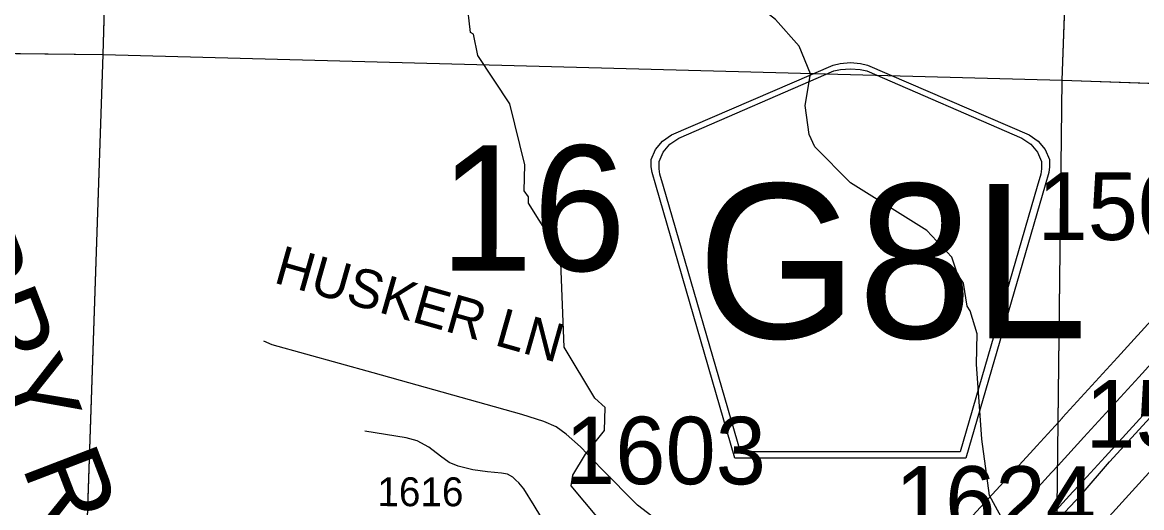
# Model space of a CAD drawing. Extents: x -132.8 to -73.3, y -60 to -26.
# Drawn here: x -119.904 to -118.744, y -46.837 to -46.334 of the extents above; entities that cross this region are included whole.
import ezdxf

# ---------------------------------------------------------------- set-up
doc = ezdxf.new("R2010")
doc.units = 0
for name, color, linetype in [('tdCoHydroRiver', 7, 'Continuous'), ('tdCoRRCL', 7, 'Continuous'), ('tdCoSecRdNmbr', 7, 'Continuous'), ('tdCoSecRdTxt', 7, 'Continuous'), ('tdCoSecRteBand', 7, 'Continuous'), ('tdCoSecRteCL', 7, 'Continuous'), ('tdCoSectLine', 7, 'Continuous'), ('tdCoSectLinePart', 7, 'Continuous'), ('tdCoSectNmbr', 7, 'Continuous'), ('tdCoShieldCoRteHrd', 7, 'Continuous'), ('tdCoSurfAsphalt', 7, 'Continuous'), ('tdCoSurfBitumUnbanded', 7, 'Continuous'), ('tdCoSurfGravelUnbanded', 7, 'Continuous')]:
    doc.layers.add(name, color=color, linetype=linetype)

msp = doc.modelspace()

# ---------------------------------------------------------------- linework, layer by layer
at = {"layer": 'tdCoHydroRiver'}
for points in [[(-118.848, -46.9334), (-118.8523, -46.9191), (-118.8532, -46.8938), (-118.8654, -46.8777), (-118.8838, -46.8583), (-118.9019, -46.8247), (-118.9098, -46.7661), (-118.9156, -46.6886), (-118.9147, -46.6571), (-118.922, -46.6332), (-118.925, -46.6284), (-118.9291, -46.6046), (-118.9351, -46.595), (-118.941, -46.5775), (-118.9671, -46.55), (-119.0462, -46.5005), (-119.0831, -46.4632), (-119.0891, -46.4504), (-119.093, -46.4203), (-119.0874, -46.3874), (-119.0992, -46.3586), (-119.1238, -46.3312), (-119.1949, -46.2756), (-119.2146, -46.2451)], [(-119.2684, -46.8952), (-119.3356, -46.8145), (-119.3338, -46.8035), (-119.3206, -46.7818), (-119.3009, -46.7571), (-119.3003, -46.7334), (-119.3111, -46.7237), (-119.3428, -46.6707), (-119.3465, -46.5744), (-119.3798, -46.5214), (-119.3797, -46.5151), (-119.3842, -46.5087), (-119.3835, -46.4819), (-119.3992, -46.4184), (-119.4325, -46.3686), (-119.4367, -46.3464), (-119.4398, -46.3447), (-119.4436, -46.3115)]]:
    msp.add_lwpolyline(points, dxfattribs=at)
at = {"layer": 'tdCoRRCL'}
for points in [[(-118.6614, -46.7183), (-118.8296, -46.903), (-118.9989, -47.0882), (-119.1678, -47.271), (-119.3407, -47.4557), (-119.5564, -47.6045), (-119.6104, -47.658)], [(-118.8522, -46.8721), (-118.8071, -46.8238), (-118.7777, -46.7899), (-118.7089, -46.7147)]]:
    msp.add_lwpolyline(points, dxfattribs=at)
at = {"layer": 'tdCoSecRteBand'}
for points in [[(-118.9556, -46.8847), (-118.8871, -46.8105), (-118.8598, -46.7806), (-118.8531, -46.7732), (-118.8265, -46.744), (-118.8264, -46.744), (-118.8264, -46.7439), (-118.7692, -46.6816), (-118.6858, -46.5898)], [(-118.725, -46.7221), (-118.7822, -46.7844), (-118.8087, -46.8136), (-118.8155, -46.821), (-118.8428, -46.851)]]:
    msp.add_lwpolyline(points, dxfattribs=at)
at = {"layer": 'tdCoSecRteCL'}
for points in [[(-119.0408, -47.0229), (-119.0016, -46.9797), (-118.9335, -46.905), (-118.865, -46.8308), (-118.8376, -46.8008), (-118.8309, -46.7934), (-118.8043, -46.7642), (-118.7471, -46.7018), (-118.6635, -46.6098), (-118.6359, -46.5785), (-118.6295, -46.5712)], [(-119.2416, -46.8539), (-119.267, -46.8347), (-119.3042, -46.7969), (-119.3259, -46.7742), (-119.3407, -46.7609), (-119.3513, -46.7535), (-119.3641, -46.7478), (-119.3866, -46.7407), (-119.5409, -46.6973), (-119.6455, -46.6684), (-119.6541, -46.6647)], [(-119.1735, -47.1676), (-119.2374, -47.061), (-119.32, -46.9239), (-119.374, -46.8351), (-119.3846, -46.8179), (-119.3898, -46.8115), (-119.3929, -46.8086), (-119.3959, -46.8058), (-119.4016, -46.8026), (-119.4078, -46.8016), (-119.4223, -46.8001), (-119.4376, -46.7982), (-119.4526, -46.7942), (-119.462, -46.7905), (-119.4711, -46.7838), (-119.483, -46.7745), (-119.4953, -46.7681), (-119.5067, -46.7649), (-119.5496, -46.758)]]:
    msp.add_lwpolyline(points, dxfattribs=at)
at = {"layer": 'tdCoSectLine'}
for points in [[(-119.8208, -46.3675), (-119.792, -45.3916), (-119.7905, -45.3743)], [(-118.8266, -46.394), (-118.791, -45.4085)], [(-120.8208, -46.3553), (-119.8208, -46.3675)], [(-119.8544, -47.3689), (-119.8208, -46.3675)], [(-119.8208, -46.3675), (-118.8266, -46.394)], [(-118.8386, -47.3987), (-118.8266, -46.394)], [(-118.8266, -46.394), (-117.8224, -46.4294)]]:
    msp.add_lwpolyline(points, dxfattribs=at)
at = {"layer": 'tdCoSectLinePart'}
for points in [[(-118.8266, -46.394), (-118.8153, -46.0816)], [(-119.8208, -46.3675), (-119.814, -46.1384)], [(-120.0927, -46.3642), (-119.8208, -46.3675)], [(-119.8428, -47.0225), (-119.8208, -46.3675)], [(-119.8208, -46.3675), (-118.8266, -46.394)], [(-118.8308, -46.7484), (-118.8266, -46.394)], [(-118.8266, -46.394), (-118.7058, -46.3982)]]:
    msp.add_lwpolyline(points, dxfattribs=at)
at = {"layer": 'tdCoShieldCoRteHrd'}
for points in [[(-119.166, -46.7858), (-119.248, -46.5029), (-119.2518, -46.4898), (-119.2526, -46.4839), (-119.2526, -46.4761), (-119.2483, -46.4658), (-119.241, -46.4573), (-119.2315, -46.4506), (-119.0642, -46.3783), (-119.0567, -46.3766), (-119.0462, -46.3757), (-119.0358, -46.3766), (-119.0283, -46.3783), (-118.861, -46.4506), (-118.8515, -46.4573), (-118.8442, -46.4658), (-118.8399, -46.4761), (-118.8399, -46.4839), (-118.8407, -46.4898), (-118.8445, -46.5029), (-118.9265, -46.7858)], [(-119.1601, -46.7795), (-119.2399, -46.5042), (-119.2436, -46.4916), (-119.2443, -46.4859), (-119.2443, -46.4784), (-119.2402, -46.4685), (-119.2333, -46.4604), (-119.2241, -46.454), (-119.0635, -46.3845), (-119.0563, -46.383), (-119.0462, -46.3821), (-119.0362, -46.383), (-119.029, -46.3845), (-118.8684, -46.454), (-118.8592, -46.4604), (-118.8523, -46.4685), (-118.8482, -46.4784), (-118.8482, -46.4859), (-118.8489, -46.4916), (-118.8526, -46.5042), (-118.9323, -46.7795)]]:
    msp.add_lwpolyline(points, close=True, dxfattribs=at)
at = {"layer": 'tdCoSurfAsphalt'}
msp.add_lwpolyline([(-119.3689, -47.3818), (-119.3495, -47.3605), (-119.3311, -47.3404), (-119.32, -47.3282), (-119.2719, -47.2754), (-119.2562, -47.2585), (-119.2381, -47.2389), (-119.1937, -47.1896), (-119.1735, -47.1676), (-119.1513, -47.1432), (-119.1093, -47.0979), (-119.0635, -47.0478), (-119.0408, -47.0229), (-119.0016, -46.9797), (-118.9335, -46.905), (-118.865, -46.8308), (-118.8376, -46.8008), (-118.8309, -46.7934), (-118.8043, -46.7642), (-118.7471, -46.7018), (-118.6635, -46.6098)], dxfattribs=at)
at = {"layer": 'tdCoSurfBitumUnbanded'}
msp.add_lwpolyline([(-119.1735, -47.1676), (-119.2374, -47.061), (-119.32, -46.9239), (-119.374, -46.8351), (-119.3846, -46.8179), (-119.3898, -46.8115), (-119.3929, -46.8086)], dxfattribs=at)
at = {"layer": 'tdCoSurfGravelUnbanded'}
for points in [[(-119.2416, -46.8539), (-119.267, -46.8347), (-119.3042, -46.7969), (-119.3259, -46.7742), (-119.3407, -46.7609), (-119.3513, -46.7535), (-119.3641, -46.7478), (-119.3866, -46.7407), (-119.5409, -46.6973), (-119.6455, -46.6684), (-119.6541, -46.6647)], [(-119.3929, -46.8086), (-119.3959, -46.8058), (-119.4016, -46.8026), (-119.4078, -46.8016), (-119.4223, -46.8001), (-119.4376, -46.7982), (-119.4526, -46.7942), (-119.462, -46.7905), (-119.4711, -46.7838), (-119.483, -46.7745), (-119.4953, -46.7681), (-119.5067, -46.7649), (-119.5496, -46.758)]]:
    msp.add_lwpolyline(points, dxfattribs=at)

# ---------------------------------------------------------------- texts
at = {"layer": 'tdCoSecRdNmbr'}
for s, height, rotation, p in [('1504', 0.07, 359.9113, (-118.8523, -46.5596)), ('1510', 0.07, 359.9107, (-118.8027, -46.7749)), ('1603', 0.07, 359.9107, (-119.342, -46.8128)), ('1624', 0.07, 359.9107, (-119.0001, -46.8641)), ('1616', 0.03, 359.9106, (-119.5365, -46.8357))]:
    msp.add_text(s, height=height, rotation=rotation, dxfattribs=at).set_placement(p)
at = {"layer": 'tdCoSecRdTxt'}
for s, height, rotation, p in [('PERRY RD', 0.08, 291, (-120.048, -46.4226)), ('HUSKER LN', 0.04, 344.1945, (-119.6451, -46.6036))]:
    msp.add_text(s, height=height, rotation=rotation, dxfattribs=at).set_placement(p)
at = {"layer": 'tdCoSectNmbr'}
msp.add_text('16', height=0.13, rotation=359.9106, dxfattribs=at).set_placement((-119.4721, -46.5915))
at = {"layer": 'tdCoShieldCoRteHrd'}
msp.add_text('G8L', height=0.16, dxfattribs=at).set_placement((-119.205, -46.6616))

doc.saveas('drawing.dxf')
